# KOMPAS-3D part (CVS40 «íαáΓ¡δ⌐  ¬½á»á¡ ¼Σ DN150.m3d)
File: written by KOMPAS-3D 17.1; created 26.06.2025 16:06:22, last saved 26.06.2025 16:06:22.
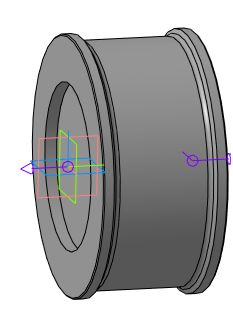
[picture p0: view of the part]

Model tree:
1. Эскиз:1
2. Элемент вращения:1
     Угол 1 = 360
3. Присоединительная точка:1
4. Присоединительная точка:2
